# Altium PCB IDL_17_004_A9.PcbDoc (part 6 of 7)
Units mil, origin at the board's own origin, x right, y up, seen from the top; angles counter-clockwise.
Board outline 9493.25 x 7199.68 mil, 6 copper layers (Top Layer - SIG1, Layer 2 - GND1, Layer 3 - PWR1, Layer 4 - PWR2, Layer 5 - GND2, Bottom Layer - SIG2), stack 60.592 mil thick; 403 components, 274 nets, 1834 pads, 1849 vias.
Unrouted connection lines stored in the file: 1.
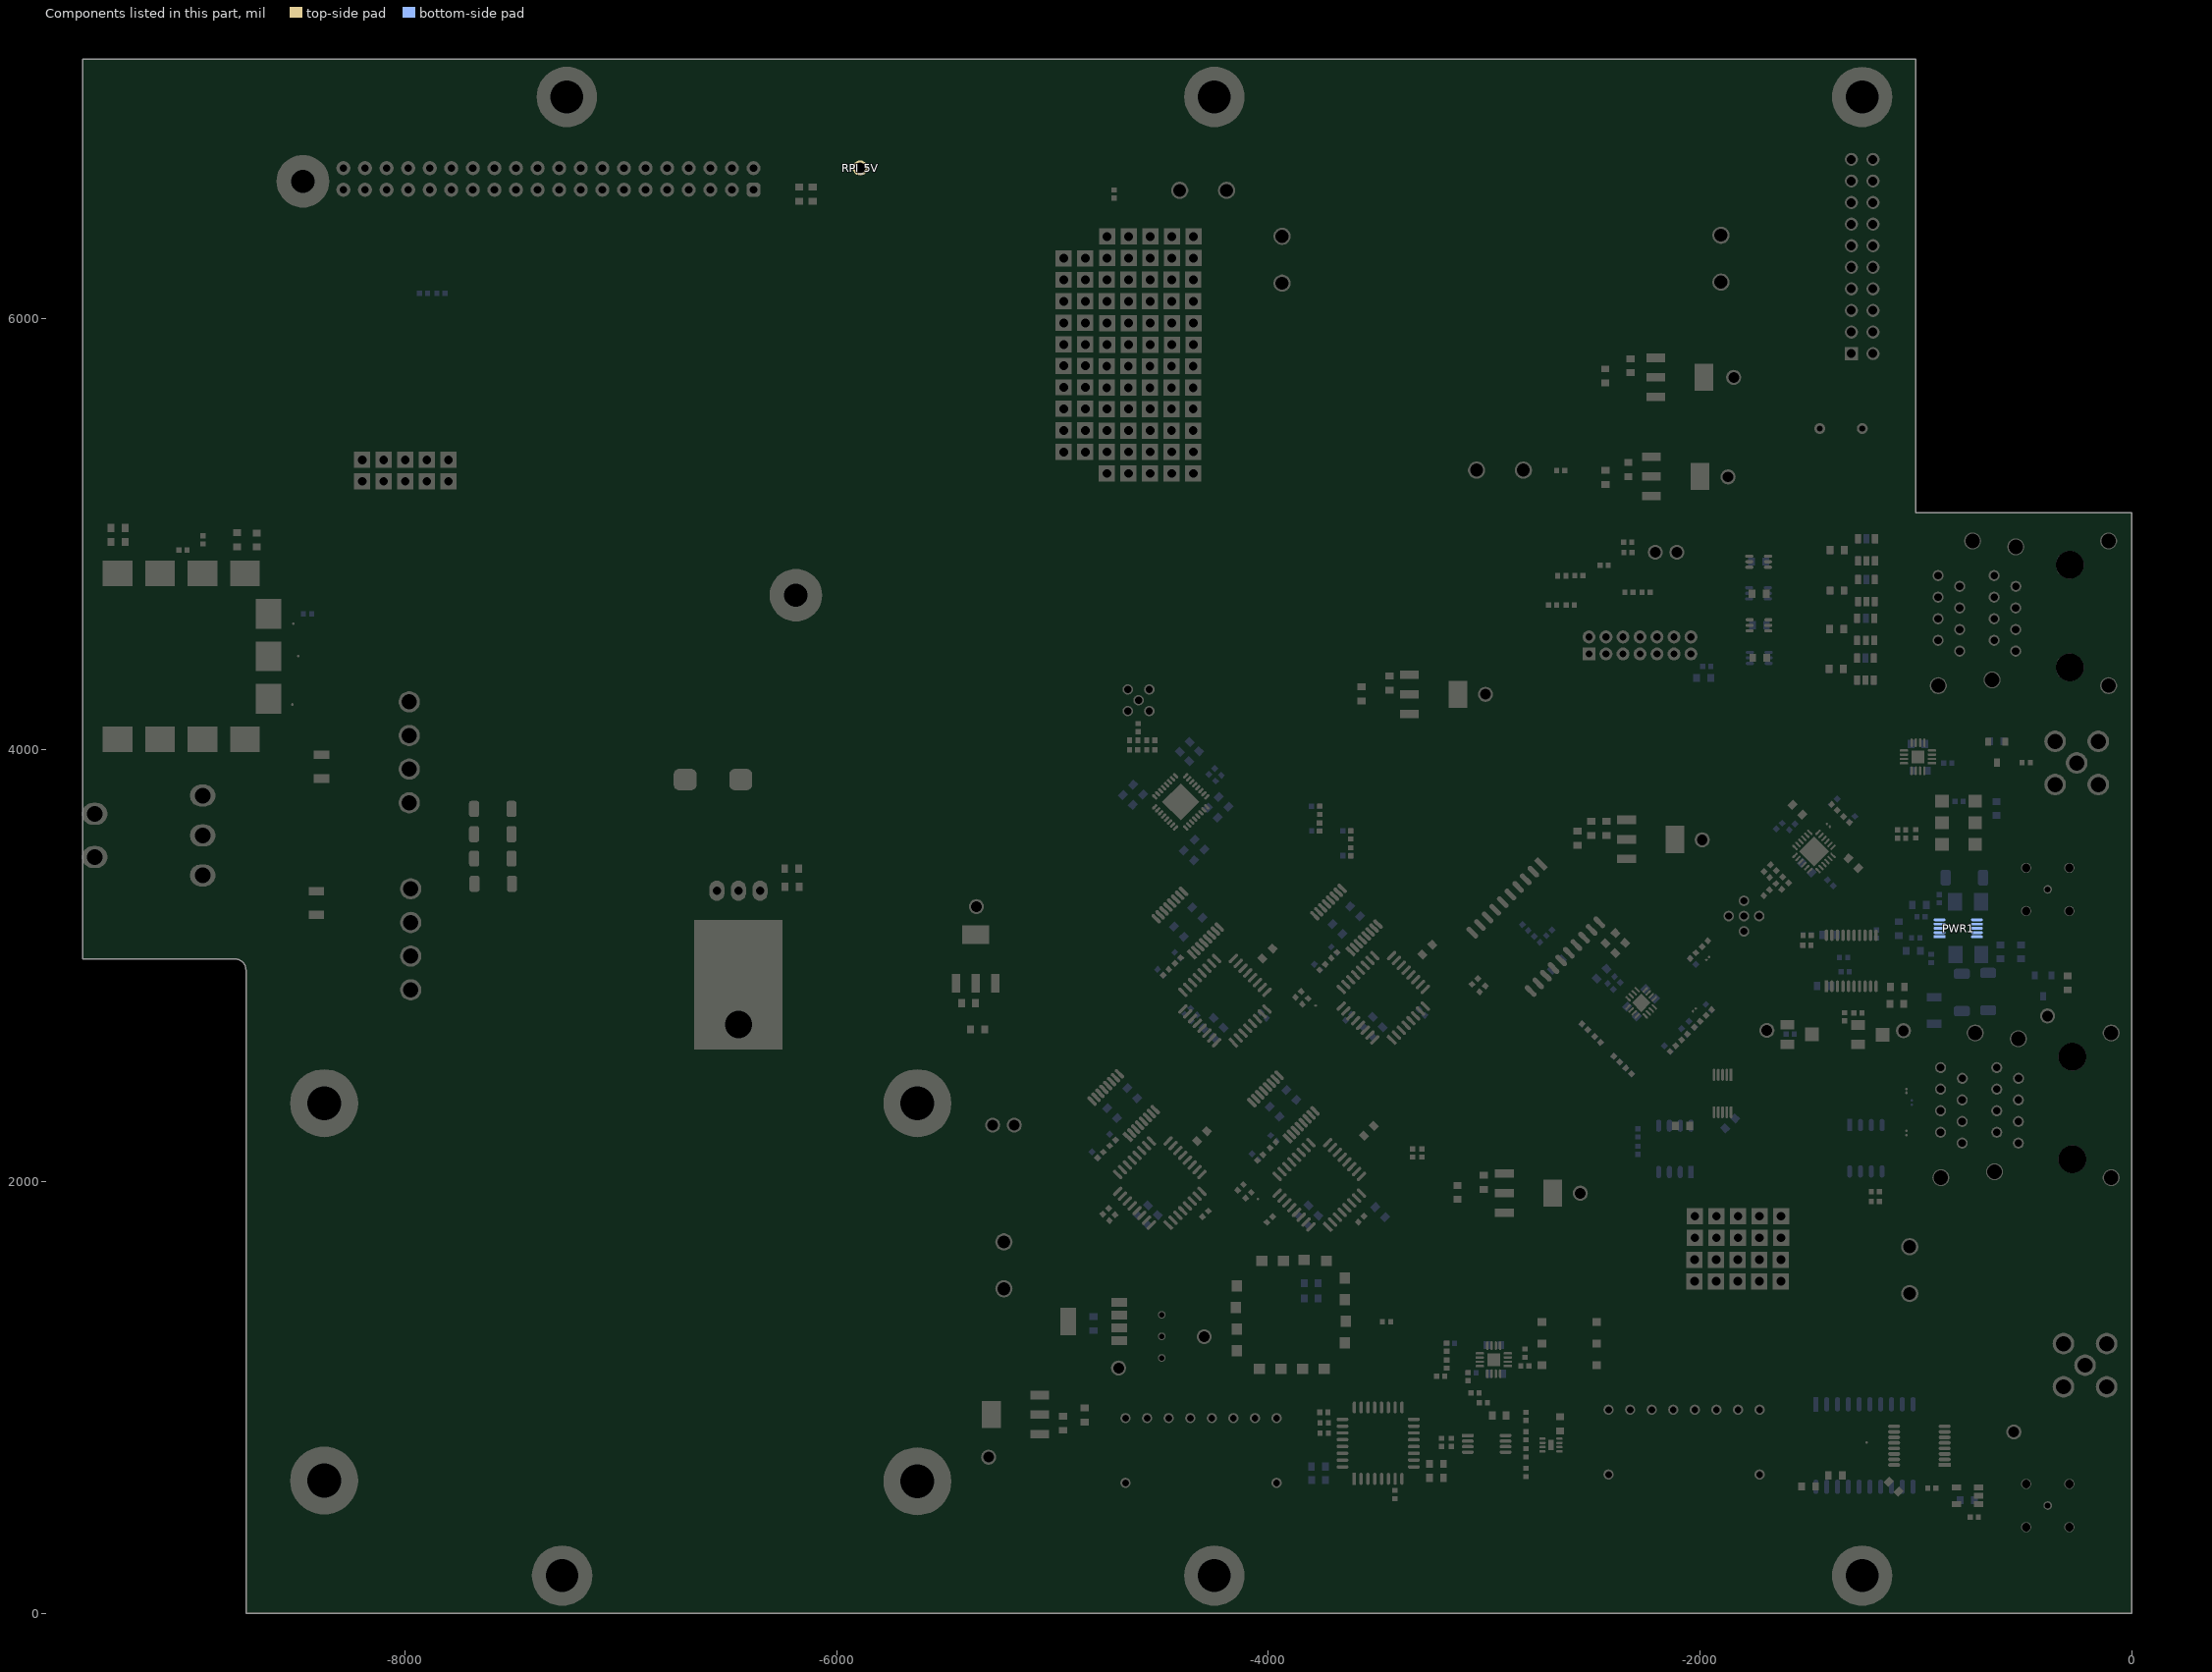
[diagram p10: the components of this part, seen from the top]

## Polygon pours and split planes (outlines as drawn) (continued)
RPI_5V on Layer 3 - PWR1 (split plane): -1020.57,7179.37 -1020.57,6052.09 -2668,6052.09 -2670.61,6051.74 -2673.04,6050.73 -2675.13,6049.13 -2676.74,6047.04 -2677.74,6044.61 -2678.09,6042 -2678.09,5501.17 -5556.91,5501.17 -5559.52,5500.83 -5561.96,5499.82 -5564.05,5498.22 -5575.13,5487.13 -5576.74,5485.04 -5577.74,5482.61 -5578.09,5480 -5578.09,4818.7 -5580.13,4817.13 -5581.74,4815.04 -5582.74,4812.61 -5583.09,4810 -5583.09,4194.17 -5583.13,4194.13 -5584.74,4192.04 -5585.74,4189.61 -5586.09,4187 -5586.09,3428 -5586.09,2538.17 -5586.13,2538.13 -5587.74,2536.04 -5588.74,2533.61 -5589.09,2531 -5589.09,1696.19 -5589.74,1694.61 -5589.87,1693.67 -5590.35,1693.04 -5591.35,1690.61 -5591.7,1688 -5591.35,1685.39 -5590.35,1682.96 -5590.09,1682.62 -5590.09,1125.19 -5590.74,1123.61 -5591.09,1121 -5591.09,19.96 -8716.11,19.88 -8714.77,2979.65 -8714.77,2979.66 -8714.96,2981.61 -8715.15,2983.58 -8715.72,2985.47 -8716.29,2987.35 -8716.3,2987.35 -8716.46,2987.67 -8716.48,2988 -8717.5,2994.9 -8719.2,3001.67 -8721.55,3008.24 -8724.53,3014.55 -8728.12,3020.53 -8732.28,3026.14 -8736.96,3031.31 -8742.14,3036 -8747.74,3040.16 -8753.73,3043.74 -8760.04,3046.73 -8766.61,3049.08 -8773.38,3050.77 -8780.28,3051.8 -8787.06,3052.13 -8787.25,3052.15 -8787.26,3052.15 -8787.27,3052.15 -9472.66,3051.48 -9473.15,7179.37
"RAW PWR" on Layer 4 - PWR2 (split plane): -1020.57,7179.37 -1020.57,5098.53 -1020.19,5094.61 -1019.04,5090.84 -1017.19,5087.37 -1014.69,5084.32 -1011.64,5081.82 -1008.17,5079.97 -1004.4,5078.82 -1000.48,5078.44 -20.12,5078.44 -20.1,20.1 -8716.11,19.88 -8714.77,2979.65 -8714.77,2979.66 -8714.96,2981.61 -8715.15,2983.58 -8715.72,2985.47 -8716.29,2987.35 -8716.3,2987.35 -8716.46,2987.67 -8716.48,2988 -8717.5,2994.9 -8719.2,3001.67 -8721.55,3008.24 -8724.53,3014.55 -8728.12,3020.53 -8732.28,3026.14 -8736.96,3031.31 -8742.14,3036 -8747.74,3040.16 -8753.73,3043.74 -8760.04,3046.73 -8766.61,3049.08 -8773.38,3050.77 -8780.28,3051.8 -8787.06,3052.13 -8787.25,3052.15 -8787.26,3052.15 -8787.27,3052.15 -9472.66,3051.48 -9473.15,7179.37
GND on Layer 5 - GND2 (split plane): -1020.57,7179.37 -1020.57,5098.53 -1020.19,5094.61 -1019.04,5090.84 -1017.19,5087.37 -1014.69,5084.32 -1011.64,5081.82 -1008.17,5079.97 -1004.4,5078.82 -1000.48,5078.44 -20.12,5078.44 -20.1,20.1 -8716.11,19.88 -8714.77,2979.65 -8714.77,2979.66 -8714.96,2981.61 -8715.15,2983.58 -8715.72,2985.47 -8716.29,2987.35 -8716.3,2987.35 -8716.46,2987.67 -8716.48,2988 -8717.5,2994.9 -8719.2,3001.67 -8721.55,3008.24 -8724.53,3014.55 -8728.12,3020.53 -8732.28,3026.14 -8736.96,3031.31 -8742.14,3036 -8747.74,3040.16 -8753.73,3043.74 -8760.04,3046.73 -8766.61,3049.08 -8773.38,3050.77 -8780.28,3051.8 -8787.06,3052.13 -8787.25,3052.15 -8787.26,3052.15 -8787.27,3052.15 -9472.66,3051.48 -9473.15,7179.37

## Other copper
Top Layer - SIG1:
  region net GND: -6245.22,6554.42 -6245.22,6433.18 -6077.92,6433.18 -6077.92,6554.42
  rectangle net JTAG_3V3: -8598.56,5000.27 -4971.56,5052.27
  rectangle net GND: -8808.78,4890.7 -8634.78,4947.76
  rectangle net JTAG_3V3: -9313.4,5000.34 -8596.4,5052.34
  rectangle net GND: -3144.97,1961.83 -3100.97,2067.83
  rectangle net "RAW PWR": -3147.07,1829.6 -3103.07,1935.6
  rectangle net GND: -2460,5278 -2418,5383
  rectangle net "RAW PWR": -2461.11,5142.48 -2417,5249
  rectangle net GND: -7531.91,3556.05 -7083.91,3764.38
  region net "RAW PWR": -7086.91,3331.05 -7086.91,3533.05 -7533.91,3533.05 -7533.91,3331.05
  region net GND: -6137,3213 -6251,3213 -6251,2610 -6137,2610
  region net GND: -6659.19,3213.23 -6773.19,3213.23 -6773.19,2613.23 -6659.19,2613.23
  region net GND: -6414,3742 -6497,3742 -6497,3199 -6414,3199
  region net RPI_5V: -6511.94,3736 -6773.19,3736 -6773.19,3282.23 -6511.94,3282.23
  rectangle net "RAW PWR": -6397,3253.23 -6219.97,3607
  region net GND: -2083.11,5382.76 -2461.11,5382.76 -2461.11,5317.08 -2083.11,5317.08
  region net "RAW PWR": -2083.11,5212.48 -2461.11,5212.48 -2461.11,5142.48 -2083.11,5142.48
  rectangle net 5VAUX: -5149.12,972.44 -4830.67,1042.44
  rectangle net GND: -5208.67,797.24 -4830.67,867.24
  rectangle net GND: -2463.93,5791.99 -2081.51,5861.99
  region net GND: -5407.71,2683.59 -5407.71,3061.59 -5470.98,3061.59 -5470.98,2683.59
  rectangle net "RAW PWR": -3146.94,1829.52 -2768.94,1890.92
  rectangle net GND: -3144.97,2008.52 -2766.97,2067.83
  region net "RAW PWR": -5233.66,2680.64 -5233.66,3058.64 -5303.66,3058.64 -5303.66,2680.64
  rectangle net "RAW PWR": -2461.93,5598.94 -2080.98,5668.94
  region net GND: -4888.6,1423.81 -5008.68,1423.81 -5008.68,1283.06 -4888.6,1283.06
  rectangle net GND: -3590.29,4325.17 -3212.29,4379.77
  rectangle net "RAW PWR": -3587.29,4132.77 -3209.29,4191.17
  rectangle net GND: -2589.43,3653.38 -2211.43,3714.08
  rectangle net "RAW PWR": -2586.43,3464.08 -2208.43,3534.08
  rectangle net 5VAUX: -4774.6,1358.06 -4461.6,1403.86
  rectangle net "RAW PWR": -4775.6,1416.06 -4462.6,1461.86
  rectangle net JTAG_3V3: -9312.36,4768.21 -9261.85,5051.31
  rectangle net NetJTAGDB_9: -9005.36,4832.21 -8866.36,4950.51
  rectangle net "RAW PWR": -2588.84,3465.38 -2544.84,3576.38
  rectangle net GND: -2589.6,3602.38 -2545.6,3713.38
  rectangle net "RAW PWR": -3589.75,4135.17 -3545.75,4246.17
  rectangle net GND: -3591.75,4269.17 -3547.75,4380.17
  region net RPI_5V: -6650,3736 -6650,3955 -6773,3955 -6773,3736
  region net GND: -6384,3667.43 -6384,3954.37 -6496.91,3954.37 -6496.91,3667.43
  region net GND: -6136,2617 -6136,3664 -6192,3664 -6192,2617
  region net GND: -6137,3654 -6137,3740 -6497,3740 -6497,3654
  rectangle net 5VAUX: -4872.35,934.35 -4830.35,1042.35
  rectangle net GND: -4872.67,797.24 -4830.67,905.24
  rectangle net "RAW PWR": -2461.93,5610.94 -2413.93,5719.94
  rectangle net GND: -2463.93,5737.94 -2415.93,5846.94
  rectangle net 3V3AUX: -3041.36,1225.35 -2980.5,1255.37
  rectangle net GND: -8740,0 0,360
  rectangle net GND: -9490,6840 -1000.48,7199.47
  rectangle net GND: -9417.73,4939.74 -9343.57,5050.98
  rectangle net GND: -6677.28,2583.15 -6214.6,2628.01
  rectangle net GND: -6686.79,3194.13 -6197.36,3239.09
  pour cut-out: -3609.85,1409.98 -3602.12,1406.78 -3595.47,1401.68 -3590.56,1395.27 -3498.05,1395.27 -3488.27,1395.92 -3487.16,1396.19 -3486.25,1396.18 -3483.67,1396.52 -3460.05,1396.52 -3451.75,1395.42 -3444.01,1392.22 -3437.37,1387.12 -3432.27,1380.48 -3429.07,1372.74 -3427.98,1364.44 -3427.98,1339.24 -3429.07,1330.94 -3432.27,1323.21 -3437.37,1316.56 -3444.01,1311.47 -3451.75,1308.26 -3460.05,1307.17 -3483.67,1307.17 -3491.97,1308.26 -3497.93,1310.73 -3590.56,1310.73 -3595.47,1304.32 -3602.12,1299.22 -3609.85,1296.02 -3618.15,1294.93 -3666.15,1294.93 -3674.46,1296.02 -3682.19,1299.22 -3688.83,1304.32 -3693.93,1310.96 -3697.14,1318.7 -3698.23,1327 -3698.23,1379 -3697.14,1387.3 -3693.93,1395.04 -3688.83,1401.68 -3682.19,1406.78 -3674.46,1409.98 -3666.15,1411.07 -3618.15,1411.07
  pour cut-out: -2705.63,1396.75 -2698.38,1393.75 -2692.15,1388.97 -2687.38,1382.75 -2684.37,1375.5 -2683.35,1367.72 -2683.35,1332.28 -2684.37,1324.5 -2687.38,1317.26 -2692.15,1311.03 -2698.38,1306.25 -2705.63,1303.25 -2713.41,1302.23 -2752.78,1302.23 -2760.56,1303.25 -2767.8,1306.25 -2774.03,1311.03 -2775.19,1312.55 -3408.83,1312.55 -3414.48,1310.21 -3422.26,1309.19 -3445.88,1309.19 -3453.66,1310.21 -3460.91,1313.21 -3467.13,1317.99 -3471.91,1324.22 -3474.91,1331.46 -3475.94,1339.24 -3475.94,1364.44 -3474.91,1372.22 -3471.91,1379.47 -3467.13,1385.69 -3460.91,1390.47 -3453.66,1393.47 -3445.88,1394.5 -3422.26,1394.5 -3414.48,1393.47 -3408.54,1391.01 -2771.36,1391.01 -2771.29,1391.07 -2770.78,1391.57 -2770.22,1391.89 -2767.8,1393.75 -2764.66,1395.05 -2763.96,1395.45 -2763.26,1395.63 -2760.56,1396.75 -2757.32,1397.18 -2756.36,1397.42 -2755.48,1397.42 -2752.78,1397.77 -2713.41,1397.77
  pour cut-out: -212.81,1232.23 -199.76,1230.51 -191.67,1228.35 -179.51,1223.31 -172.26,1219.12 -161.81,1211.11 -155.89,1205.19 -147.88,1194.74 -143.69,1187.49 -138.65,1175.33 -136.49,1167.24 -134.77,1154.19 -134.77,1145.81 -136.49,1132.76 -138.65,1124.67 -143.69,1112.51 -147.88,1105.26 -155.89,1094.81 -161.81,1088.89 -172.26,1080.88 -179.51,1076.69 -191.67,1071.65 -199.76,1069.49 -212.81,1067.77 -221.19,1067.77 -234.24,1069.49 -242.33,1071.65 -254.49,1076.69 -261.74,1080.88 -272.19,1088.89 -278.11,1094.81 -278.67,1095.55 -279.5,1096.37 -287.39,1103.21 -290.16,1105.25 -292.75,1106.93 -294.8,1108.05 -296.21,1108.67 -296.44,1108.75 -2437.9,1108.75 -2439.08,1107.85 -2439.53,1107.38 -2440.3,1106.91 -2443.43,1104.51 -2446.07,1103.41 -2446.69,1103.04 -2447.66,1102.76 -2451.17,1101.3 -2453.89,1100.94 -2454.73,1100.7 -2455.94,1100.67 -2459.47,1100.21 -2498.84,1100.21 -2507.14,1101.3 -2514.88,1104.51 -2521.52,1109.6 -2526.62,1116.25 -2529.82,1123.98 -2530.91,1132.28 -2530.91,1167.72 -2529.82,1176.02 -2526.62,1183.75 -2521.52,1190.4 -2514.88,1195.49 -2507.14,1198.7 -2498.84,1199.79 -2459.47,1199.79 -2455.94,1199.33 -2454.73,1199.3 -2453.89,1199.06 -2451.17,1198.7 -2447.66,1197.24 -2446.69,1196.96 -2446.07,1196.59 -2443.43,1195.49 -2440.3,1193.09 -2439.53,1192.62 -2439.08,1192.15 -2437.9,1191.25 -296.44,1191.25 -296.21,1191.33 -294.8,1191.95 -292.75,1193.07 -290.16,1194.75 -287.08,1197.02 -283.86,1199.68 -278.28,1204.96 -278.11,1205.19 -272.19,1211.11 -261.74,1219.12 -254.49,1223.31 -242.33,1228.35 -234.24,1230.51 -221.19,1232.23 -212.81,1232.23
  pour cut-out: -603.92,3991.45 -596.18,3988.25 -589.54,3983.15 -588.7,3982.06 -534.37,3982.06 -528.75,3984.39 -520.45,3985.48 -496.83,3985.48 -488.53,3984.39 -480.79,3981.19 -474.15,3976.09 -469.05,3969.45 -465.85,3961.71 -464.75,3953.41 -464.75,3928.21 -465.85,3919.91 -469.05,3912.18 -474.15,3905.53 -480.79,3900.44 -488.53,3897.23 -496.83,3896.14 -520.45,3896.14 -528.75,3897.23 -534.37,3899.56 -590.62,3899.56 -596.18,3895.29 -603.92,3892.09 -612.22,3891 -639.78,3891 -648.08,3892.09 -655.82,3895.29 -659.02,3897.75 -888,3897.75 -891.12,3898.16 -894.26,3898.37 -897.17,3898.94 -918.29,3901.43 -946,3901.43 -954.3,3902.52 -962.04,3905.72 -968.68,3910.82 -973.78,3917.46 -976.98,3925.2 -978.07,3933.5 -978.07,3944.5 -976.98,3952.8 -973.78,3960.54 -968.68,3967.18 -962.04,3972.28 -954.3,3975.48 -946,3976.57 -919.6,3976.57 -896.41,3979.21 -894.26,3979.63 -891.12,3979.84 -888,3980.25 -664.69,3980.25 -662.46,3983.15 -655.82,3988.25 -648.08,3991.45 -639.78,3992.55 -612.22,3992.55
  pour cut-out: -251.81,4022.23 -238.76,4020.51 -230.67,4018.35 -218.51,4013.31 -211.26,4009.12 -200.81,4001.11 -194.89,3995.19 -186.88,3984.74 -182.69,3977.49 -177.65,3965.33 -175.49,3957.24 -173.77,3944.19 -173.77,3935.81 -175.49,3922.76 -177.65,3914.67 -182.69,3902.51 -186.88,3895.26 -194.89,3884.81 -200.81,3878.89 -211.26,3870.88 -218.51,3866.69 -230.67,3861.65 -238.76,3859.49 -251.81,3857.77 -260.19,3857.77 -273.24,3859.49 -281.33,3861.65 -293.49,3866.69 -300.74,3870.88 -311.19,3878.89 -317.11,3884.81 -325.12,3895.26 -327.14,3898.75 -447.06,3898.75 -450.73,3897.23 -459.03,3896.14 -482.65,3896.14 -490.96,3897.23 -498.69,3900.44 -505.33,3905.53 -510.43,3912.18 -513.64,3919.91 -514.73,3928.21 -514.73,3953.41 -513.64,3961.71 -510.43,3969.45 -505.33,3976.09 -498.69,3981.19 -490.96,3984.39 -482.65,3985.48 -459.03,3985.48 -450.73,3984.39 -443.15,3981.25 -327.14,3981.25 -325.12,3984.74 -317.11,3995.19 -311.19,4001.11 -300.74,4009.12 -293.49,4013.31 -281.33,4018.35 -273.24,4020.51 -260.19,4022.23 -251.81,4022.23
  pour cut-out: -386.1,549.68 -384.14,549.55 -376.46,548.02 -374.59,547.39 -372.66,547 -370.89,546.13 -369.03,545.5 -367.39,544.41 -365.62,543.53 -359.11,539.18 -357.63,537.88 -355.99,536.79 -354.69,535.31 -353.21,534.01 -352.12,532.37 -350.82,530.89 -346.47,524.38 -345.59,522.61 -344.5,520.97 -343.87,519.11 -343,517.34 -342.61,515.41 -341.98,513.54 -340.45,505.86 -340.32,503.9 -339.94,501.97 -340.07,500 -339.94,498.03 -340.32,496.1 -340.45,494.14 -341.98,486.46 -342.61,484.59 -343,482.66 -343.87,480.89 -344.5,479.03 -345.59,477.39 -346.47,475.62 -350.82,469.11 -352.12,467.63 -353.21,465.99 -354.69,464.69 -355.99,463.21 -357.63,462.12 -359.11,460.82 -365.62,456.47 -367.39,455.59 -369.03,454.5 -370.89,453.87 -372.66,453 -374.59,452.61 -376.46,451.98 -384.14,450.45 -386.1,450.32 -388.03,449.94 -390,450.07 -391.97,449.94 -393.9,450.32 -395.86,450.45 -403.54,451.98 -405.41,452.61 -407.34,453 -409.11,453.87 -410.97,454.5 -412.61,455.59 -414.38,456.47 -420.89,460.82 -422.37,462.12 -424.01,463.21 -425.31,464.69 -426.79,465.99 -427.88,467.63 -429.18,469.11 -429.19,469.12 -668.89,469.12 -671.35,467.24 -670.76,465.81 -669.73,458.03 -669.73,432.83 -670.76,425.05 -673.76,417.8 -678.54,411.58 -684.76,406.8 -692.01,403.8 -699.79,402.78 -723.41,402.78 -731.19,403.8 -738.44,406.8 -744.66,411.58 -749.44,417.8 -752.44,425.05 -753.47,432.83 -753.47,458.03 -752.44,465.81 -750.75,469.9 -752.22,471.03 -757,477.25 -760,484.5 -761.03,492.28 -761.03,519.84 -760,527.62 -757,534.87 -752.22,541.09 -746,545.87 -738.75,548.87 -730.97,549.9 -687.66,549.9 -679.88,548.87 -672.63,545.87 -668.89,543 -415.18,543 -414.38,543.53 -412.61,544.41 -410.97,545.5 -409.11,546.13 -407.34,547 -405.41,547.39 -403.54,548.02 -395.86,549.55 -393.9,549.68 -391.97,550.06 -390,549.93 -388.03,550.06
  pour cut-out: -1294.46,4403.63 -1176.5,4403.63 -1175.52,4344.77 -1294.21,4344.77
  pour cut-out: -1293.84,4588.59 -1175.88,4588.59 -1174.9,4529.74 -1293.59,4529.74
  pour cut-out: -1289.79,4766.09 -1171.84,4766.09 -1170.85,4707.23 -1289.54,4707.23
  pour cut-out: -1288.17,4955.18 -1170.22,4955.18 -1169.24,4896.32 -1287.93,4896.32
  pour cut-out: -644.18,4066.63 -598.92,4065.53 -598.42,4009.09 -643.93,4009.46
  pour cut-out: -1581.7,3711.86 -1543.19,3753.39 -1518.91,3732.62 -1559.93,3692.61
  pour cut-out: -1321.96,3465.21 -1282.23,3506.33 -1259.25,3483.07 -1299.39,3442.24
  pour cut-out: -1103.26,2919.43 -1069.54,2919.43 -1069.54,2807.75 -1105.69,2807.75 -1105.69,2844.98 -1120.53,2844.98 -1120.53,2880.32 -1105.96,2880.32
  pour cut-out: -325.98,2937.72 -325.98,2937.91 -268.78,2937.91 -268.78,2904.54 -326.26,2904.54
  pour cut-out: -2472.14,5745.43 -2418.95,5745.43 -2418.95,5795.86 -2060.24,5795.86 -2060.24,5769.54 -2386.95,5769.54 -2386.95,5693.66 -2060.25,5693.66 -2053.06,5598.87 -2077.93,5598.87 -2077.93,5673.3 -2382.39,5673.3 -2418.95,5673.3 -2418.95,5719.25 -2472.14,5719.25
  pour cut-out: -2471.31,5276.64 -2416.48,5276.64 -2416.48,5327.07 -2070.82,5327.07 -2070.82,5299.46 -2384.48,5299.46 -2384.48,5224.86 -2057.78,5224.86 -2056.53,5204.51 -2379.92,5204.51 -2416.48,5204.51 -2416.48,5250.46 -2471.31,5250.46
  pour cut-out: -1230.35,2757.54 -1230.35,2757.5 -1175.02,2757.5 -1175.02,2603.5 -1230.97,2603.5 -1230.97,2662.46 -1310.87,2662.46 -1310.87,2699.82 -1231.47,2699.82
  pour cut-out: -2598.09,3602.94 -2545.51,3602.94 -2545.51,3653.37 -2205.04,3653.37 -2205.04,3627.05 -2523.01,3627.05 -2523.01,3551.16 -2196.32,3551.16 -2195.07,3530.81 -2518.46,3530.81 -2542,3530.81 -2542,3576.76 -2598.09,3576.76
  pour cut-out: -2084.89,1894.46 -1562.65,1894.46 -1562.65,1485.39 -2079.44,1485.39 -2084.89,1490.85
  pour cut-out: -3156.49,1961.53 -3100.55,1961.53 -3100.55,2008.48 -3080.47,2008.48 -2766.06,2008.48 -2766.06,1985.63 -3080.47,1985.63 -3080.47,1954.04 -3080.47,1909.75 -2757.33,1909.75 -2756.08,1889.4 -3079.47,1889.4 -3103.02,1889.4 -3103.02,1935.35 -3156.49,1935.35
  pour cut-out: -4990.4,5337.13 -4796.32,5330.07 -4796.32,5232.69 -4302.06,5238.33 -4301.16,5293.46 -4301.16,5343.98 -4301.16,6332.1 -5002.6,6332.1
  region net GND: -9065.24,4759.31 -9065.55,4886.38 -9047.3,4904.62 -9047.3,4949.38 -9080.76,4982.84 -9187.85,4982.84 -9205.9,4964.8 -9205.9,4878.95 -9203.13,4876.18 -9203.13,4759.31 -9201.89,4759.93 -9070.8,4759.93
  region net RPI_5V: -6518.61,6645.52 -6536.94,6663.84 -6536.94,6714.11 -6504.23,6746.81 -6133.89,6746.81 -6133.89,6632.18 -6190.13,6588.79 -6295.13,6588.79 -6351.86,6645.52
  region net DIS3V3: -1297.26,5583.46 -1234.18,5646.55 -1234.18,5858.12 -1208.94,5883.35 -1116.74,5883.35 -1080.84,5847.45 -1080.84,5522.32 -1204.09,5399.07 -1304.05,5399.07 -1340.93,5435.95 -1340.93,5538.82 -1290.47,5589.29
  region net RF_3V3: -4537.66,3706.45 -4509.14,3734.98 -4507.45,3734.98 -4502.88,3730.42 -4568.77,3664.53 -4614.14,3664.53 -4622.05,3672.44 -4622.06,3747.23 -4575.52,3793.76 -4563.76,3805.52 -4563.2,3804.96 -4540.08,3804.96 -4516.25,3781.12 -4516.25,3773.56 -4517.9,3771.91 -4524.66,3772.06 -4542.9,3790.3 -4552.67,3790.3 -4554.22,3790.16 -4554.37,3788.6 -4548.68,3782.69 -4532.94,3766.32 -4532.94,3757.77 -4542.33,3748.38 -4566.4,3748.38 -4573.73,3755.71 -4587.26,3755.71 -4598.73,3744.24 -4598.73,3717.71 -4587.48,3706.45
  region net 3V3AUX: -3697.83,615.63 -3652.65,660.81 -3636.64,660.81 -3622.36,646.54 -3622.36,630.18 -3667.88,584.73 -3688.16,584.73 -3697.83,594.4
  region net BMB_3V3: -3791.58,1717.3 -3781.58,1707.3 -3753.71,1707.3 -3743.35,1717.18 -3743.36,1764.01 -3725.68,1781.69 -3738.97,1794.98 -3766.44,1767.51 -3794.39,1795.46 -3807.27,1782.58 -3791.58,1766.89
  region net BMA_3V3: -4222.35,2598.52 -4213.27,2589.44 -4184.43,2589.44 -4176.52,2596.99 -4176.53,2632.7 -4157.95,2651.27 -4176.53,2669.31 -4187.57,2658.26 -4202.05,2643.79 -4223.11,2664.86 -4229.83,2665.17 -4242.08,2652.92 -4222.35,2633.18
  region net BMA_3V3: -3493.38,2601.91 -3486.8,2595.33 -3453.06,2595.33 -3445.16,2602.87 -3445.16,2638.58 -3427.49,2656.26 -3440.78,2669.55 -3468.25,2642.08 -3496.2,2670.03 -3509.07,2657.15 -3493.38,2641.46
  region net BMB_3V3: -4527.75,1729.36 -4513.21,1714.82 -4496.22,1714.82 -4479.52,1730.76 -4479.53,1772.2 -4461.85,1789.88 -4475.14,1803.17 -4502.61,1775.7 -4530.56,1803.65 -4543.44,1790.77 -4527.75,1775.08
  region net RPI_5V: -6196.77,6589.06 -6197.55,6589.06 -6224.04,6615.56 -6224.04,6746.81 -6070.45,6746.81 -6037.77,6714.14 -6037.77,6635.07 -6083.78,6589.06
  region net NetF0_1: -8449.01,3256.84 -8474.74,3231.11 -8474.74,3041.55 -8413.66,2980.46 -8095.44,2980.46 -7902.92,2980.46 -7844.79,3038.6 -7844.79,3246.66 -7872.66,3274.53 -7932.89,3274.53 -8386.55,3274.53
  region net NetD5_1: -9201.72,3638.31 -9201.72,3640.04 -9165.35,3676.4 -7869.08,3676.4 -7704.57,3840.91 -7650.15,3840.91 -7632.83,3823.6 -7636.3,3820.13 -7636.3,3295.44 -7660.54,3271.2 -7703.17,3271.2 -7962.92,3530.95 -9165.35,3530.95 -9198.26,3563.85 -9198.26,3643.5
  region net NetF1_1: -8423.48,3948.6 -8456.4,3981.52 -8456.4,4083.12 -8407.74,4131.78 -7914,4131.78 -7865.34,4083.12 -7865.34,3882.79 -7915.22,3832.92 -8173.28,3832.92 -8288.96,3948.6
  region net ACDC_PWR: -9205.1,3462.64 -9204.55,3462.64 -9172.3,3494.89 -9170.97,3493.55 -8415.19,3493.55 -8373.12,3451.49 -8373.12,3348 -8392.48,3328.64 -9183.65,3328.64 -9206.1,3351.08 -9206.1,3461.64
  region net NIM_PWR: -9189.08,3703.37 -9206.19,3720.47 -9209.19,3720.47 -9209.19,3865.86 -9187.58,3887.47 -8563.19,3887.47 -8562.29,3886.58 -8386.79,3886.58 -8351.51,3851.29 -8351.51,3720.47 -8368.61,3703.37
  region net DIS3V3: -2376.68,5765.24 -2377.68,5688.24 -2217.68,5688.24 -2052.68,5688.24 -2052.68,5613.24 -1902.68,5613.24 -1902.68,5838.24 -2052.68,5838.24 -2052.68,5763.24 -2377.68,5763.24
  region net RF_3V3: -3521.25,4291.69 -3521.25,4218.17 -3361.25,4218.17 -3196.25,4218.17 -3196.25,4143.17 -3046.25,4143.17 -3046.25,4368.17 -3196.25,4368.17 -3196.25,4293.17 -3521.25,4293.17
  region net BMA_3V3: -5393.02,2746.55 -5316.02,2745.55 -5316.02,2905.55 -5316.02,3070.55 -5241.02,3070.55 -5241.02,3220.55 -5466.02,3220.55 -5466.02,3070.55 -5391.02,3070.55 -5391.02,2745.55
  region net RM_3V3: -2516.84,3619.41 -2516.84,3550.38 -2356.84,3550.38 -2191.84,3550.38 -2191.84,3475.38 -2041.84,3475.38 -2041.84,3700.38 -2191.84,3700.38 -2191.84,3620.77 -2515.76,3620.77
  region net BMB_3V3: -3080,1987 -3081,1910 -2921,1910 -2756,1910 -2756,1835 -2606,1835 -2606,2060 -2756,2060 -2756,1985 -3081,1985
  region net JTAG_3V3: -2394.19,5288.72 -2394.78,5242.77 -2070,5242.77 -2070,5151 -1920,5151 -1920,5376 -2070,5376 -2070,5288.72
  region net 3V3AUX: -4896.12,880 -4895.12,957 -5055.12,957 -5220.12,957 -5220.12,1032 -5370.12,1032 -5370.12,807 -5220.12,807 -5220.12,882 -4895.12,882
  region net NetC28_2: -1182.75,2926.28 -1134.28,2926.28 -1125,2917 -1125,2688 -1133,2680 -1140,2687 -1174,2687 -1174,2780 -1152,2802 -1152,2856.57 -1182.36,2886.93
  region net NetB1_1: -918.22,3944.45 -889.91,3947.66 -889.91,3930.39 -918.22,3933.71
  pour cut-out: -4822.65,908.17 -4879.95,908.17 -4879.95,861.22 -4900.03,861.22 -5214.45,861.22 -5214.45,884.07 -4900.03,884.07 -4900.03,915.67 -4900.03,959.95 -5223.17,959.95 -5224.42,980.31 -4901.03,980.31 -4877.49,980.31 -4877.49,934.35 -4822.65,934.35
  pour cut-out: -5366.98,2677.3 -5366.45,2677.83 -5366.45,2726.89 -5413.4,2726.89 -5413.4,2746.97 -5413.4,3061.39 -5390.55,3061.39 -5390.55,2746.97 -5358.96,2746.97 -5314.67,2746.97 -5314.67,3070.12 -5294.32,3071.36 -5294.32,2747.98 -5294.32,2724.43 -5340.27,2724.43 -5340.27,2677.3
  pour cut-out: -3597.45,4276.53 -3590.53,4269.6 -3547.35,4269.6 -3547.35,4324.99 -3206.97,4325 -3206.97,4293.71 -3521.38,4293.71 -3521.38,4262.11 -3521.38,4217.83 -3198.24,4217.83 -3196.99,4197.47 -3520.38,4197.47 -3543.93,4197.47 -3543.93,4243.42 -3597.45,4243.42
  pour cut-out: -6202.28,6588.65 -6083.33,6588.86 -6028.22,6630.85 -6083.33,6558.8 -6082.93,6558.4 -6202.89,6558.4 -6224.1,6578.59
  pour cut-out: -4796.13,6424.54 -4301.05,6424.54 -4301.05,6331.84 -4795.08,6331.84 -4795.08,6332.37
  pour cut-out: -8246.77,5392.05 -7750.25,5392.05 -7750.25,5198.14 -8246.77,5198.14
  pour cut-out: -1359.76,3661.32 -1340.27,3661.32 cw(c-1340.27,3640) -1318.95,3640 cw(c-1331.9,3640) -1331.9,3627.06 -1340.88,3627.06 cw(c-1340.88,3652.34) -1366.16,3652.34
  pour cut-out: -8742.67,-0.11 -8736.07,2997.05 ccw(c-8796.62,2968.44) -8774.06,3031.5 -9501.28,3031.49 -9501.28,-0.12
  region net RF_3V3: -1567,3459 ccw(c-1567,3463.83) -1563.59,3460.41 -1529,3495 cw(c-1526.59,3492.59) -1526.59,3496 -1524,3496 cw(c-1524,3491.18) -1520.59,3494.59 -1511.2,3485.2 cw(c-1521.35,3477.99) -1514.24,3467.76 -1532.43,3449.57 cw(c-1555,3458.14) -1555,3434 cw(c-1555,3438.83) -1558.41,3435.41 -1568,3445 cw(c-1563.17,3449.83) -1570,3449.83 -1570,3456 cw(c-1567.49,3456.5) -1570,3457 cw(c-1567.88,3455.58) -1569.29,3457.71 -1565,3459 -1568,3459
Bottom Layer - SIG2:
  rectangle net GND: -3876.54,594.58 -3795.57,700.58
  rectangle net 3V3AUX: -3744,591.82 -3593.04,702.39
  rectangle net GND: -7531.91,3556.05 -7088.91,3764.38
  rectangle net "RAW PWR": -7533.91,3331.05 -7086.91,3533.05
  rectangle net RM_3V3: -824.11,3012.63 -784.43,3336.37
  rectangle net GND: -1577,5398 -1379,5584
  rectangle net NetC122_1: -996.63,3040.22 -869.63,3141.22
  rectangle net NetC120_2: -819,2943.76 -581,2983.13
  region net NetC120_2: -579.85,2944 -579.85,3052.13 -640,3052.13 -640,2944
  rectangle net GND: -8740,0 0,360
  rectangle net GND: -9490,6840 -1000.48,7199.47
  pour cut-out: -4311.75,3963.14 -4335.61,3939.6 -4418.72,4023.04 -4395.1,4046.82
  pour cut-out: -4377.08,3479.67 -4400.62,3503.53 -4310.03,3593.75 -4286.25,3570.13
  pour cut-out: -4266.35,3677.78 -4289.89,3701.64 -4199.59,3791.59 -4175.81,3767.97
  pour cut-out: -4595.63,3849.28 -4570.38,3823.68 -4658.57,3735.85 -4684.08,3761.19
  pour cut-out: -4839.79,1326.53 -4839.56,1360.05 -4782.37,1359.93 -4782.25,1326.42
  pour cut-out: -3818.35,1559.26 -3784.83,1559.03 -3785.08,1430.96 -3818.6,1430.84
  pour cut-out: -1829.9,2262.09 -1853.76,2238.55 -1894.13,2279.07 -1870.51,2302.85
  pour cut-out: -2324.1,2755.87 -2347.64,2779.73 -2307.12,2820.09 -2283.33,2796.48
  pour cut-out: -2239.61,2838.24 -2263.15,2862.1 -2222.62,2902.47 -2198.84,2878.85
  pour cut-out: -2696.31,3014.19 -2672.45,3037.72 -2632.09,2997.2 -2655.71,2973.42
  pour cut-out: -2488.48,2971.82 -2464.62,2995.35 -2424.26,2954.83 -2447.88,2931.05
  pour cut-out: -2972.17,1272.79 -2938.66,1272.56 -2938.77,1215.37 -2972.29,1215.25
  pour cut-out: -2962.58,1139.81 -2929.06,1139.58 -2929.17,1082.38 -2962.69,1082.27
  pour cut-out: -3737.05,666.73 -3737.28,633.22 -3794.47,633.33 -3794.59,666.85
  pour cut-out: -1746.2,4901.25 -1712.68,4901.02 -1712.8,4843.82 -1746.31,4843.71
  pour cut-out: -1742.66,4606.47 -1709.14,4606.24 -1709.25,4549.05 -1742.77,4548.93
  pour cut-out: -1382.47,4954.11 -1348.95,4953.88 -1349.06,4896.69 -1382.58,4896.57
  pour cut-out: -1382.49,4767.39 -1348.97,4767.16 -1349.09,4709.97 -1382.6,4709.85
  pour cut-out: -1384.61,4588.85 -1351.1,4588.62 -1351.21,4531.42 -1384.73,4531.31
  pour cut-out: -1386.66,4404.84 -1353.14,4404.61 -1353.25,4347.41 -1386.77,4347.3
  pour cut-out: -656.29,3746.25 -597.6,3746.67 -597.6,3710.13 -656.29,3709.16
  pour cut-out: -542.88,3081.92 -542.79,3048.07 -485.69,3048.26 -485.97,3081.83
  pour cut-out: -654.98,3079.05 -619.79,3080.34 -580.74,3081.08 -580.37,3051.78 -643.74,3052.52 -657.01,3045.7 -659.59,3070.02
  pour cut-out: -774.79,3091.31 -762.01,3091.31 -754.09,3091.31 -734.43,3057 -727.55,3004.59 -695.57,3002.79 -701.26,2990.23 -742.3,2987.05 -778.97,2993.24
  pour cut-out: -1109.33,3189.1 -1026.69,3189.24 -1025.31,3157.82 -1053.27,3158.93 -1052.44,3155.05 -1099.91,3154.36 -1106.28,3157.13 -1122.34,3158.93 -1124.69,3183.56 -1119.01,3189.52 -1108.08,3189.38
  pour cut-out: -1416.75,3172.62 -1383.41,3172.77 -1382.8,3115.22 -1417.67,3114.91
  pour cut-out: -1464.96,3172.55 -1447.98,3169.46 -1447.98,3071.36 -1464.96,3070.97
  pour cut-out: -1292.61,4589.64 -1174.65,4589.64 -1173.67,4530.78 -1292.36,4530.78
  pour cut-out: -779.19,543.61 -746.96,543.81 -746.71,496.84 -780.21,497.65
  pour cut-out: -3785.34,710.02 -3752.05,710.02 -3750.41,586.97 -3784.36,588.93
  pour cut-out: -3996.51,2322.27 -3892.5,2426.37 -3867.54,2403.76 -3974.91,2296.9
  pour cut-out: -4749.19,2315.84 -4629.99,2434.49 -4605.3,2410.54 -4725.61,2291.71
  pour cut-out: -1294.71,4404.72 -1176.76,4404.72 -1175.78,4345.87 -1294.47,4345.87
  pour cut-out: -1289.14,4766.54 -1171.19,4766.54 -1170.2,4707.69 -1288.89,4707.69
  pour cut-out: -1288.47,4955.14 -1170.52,4955.14 -1169.54,4896.29 -1288.22,4896.29
  pour cut-out: -2084.38,1892.51 -1562.13,1892.51 -1562.13,1483.44 -2078.92,1483.44 -2084.38,1488.89
  pour cut-out: -5005.01,6335.4 -5004.63,6335.77 -4300.5,6335.77 -4300.5,5328.5 -4303.1,5325.9 -5000.51,5325.9
  region net RPI_5V: -6518.61,6645.52 -6536.94,6663.84 -6536.94,6750.5 -6051.54,6750.5 -6051.54,6647.33 -6072.49,6631.16 -6337.5,6631.16 -6351.86,6645.52
  region net NetC120_1: -730.02,3068.65 -722.87,3075.8 -657.96,3075.8 -639.31,3094.46 -589.99,3094.46 -586.87,3097.58 -586.87,3127.63 -593.88,3134.63 -641.98,3134.63 -741.27,3134.63 -743.44,3132.46 -743.44,3082.07
  region net -5V: -447.09,2973.72 -497.03,3040.71 -527.12,3040.58 -531.58,3036.12 -531.58,2943.15 -513.29,2924.86 -458.03,2924.86 -447.09,2936.9
  region net GND: -3832.12,1899.28 -3760.83,1828 -3711.82,1844.47 -3693.23,1887.43 -3720.19,1914.39 -3824.34,1914.39 -3832.11,1906.61
  region net BMB_3V3: -3882.19,1855.98 -3869.95,1855.98 -3800.6,1786.63 -3725.79,1786.63 -3718.18,1779.02 -3718.18,1737.82 -3733.22,1722.87 -3838.34,1722.87 -3894.93,1779.45 -3894.93,1843.24
  region net GND: -4571.96,1902.04 -4500.68,1830.75 -4451.67,1847.22 -4433.08,1890.18 -4460.04,1917.14 -4564.18,1917.14 -4571.96,1909.37
  region net GND: -4272.4,2763.42 -4201.11,2692.13 -4133.52,2692.13 -4101.03,2719.07 -4101.03,2729.14 -4160.96,2789.07 -4254.07,2789.07 -4272.4,2770.74
  region net BMB_3V3: -4621.31,1859.96 -4595.29,1859.96 -4525.94,1790.61 -4464.9,1790.61 -4457.29,1783.01 -4457.29,1741.81 -4472.33,1726.85 -4577.45,1726.85 -4634.04,1783.44 -4634.04,1847.23
  region net BMA_3V3: -4317.32,2724.2 -4305.08,2724.2 -4235.73,2654.85 -4160.92,2654.85 -4153.31,2647.24 -4153.31,2606.05 -4168.35,2591.09 -4273.47,2591.09 -4330.06,2647.68 -4330.06,2711.47
  region net BMA_3V3: -3596.99,2708.35 -3580.06,2725.28 -3566.5,2725.28 -3500.56,2659.34 -3424.15,2659.34 -3413.26,2649.58 -3413.26,2603.17 -3420.79,2595.64 -3535.07,2595.64 -3596.99,2657.56
  region net GND: -3537.29,2763.23 -3462.46,2688.4 -3382.87,2688.4 -3332.31,2738.95 -3332.31,2743.73 -3394.26,2805.69 -3506.67,2805.69 -3537.29,2775.07
  region net GND: -6774.46,3169.66 -6730.42,3213.69 -6183.77,3213.69 -6135.17,3165.1 -6135.17,2651.85 -6174.65,2612.37 -6715.24,2612.37 -6774.46,2671.59
  region net "RAW PWR": -6378.02,3270.75 -6395.45,3292.32 -6395.45,3320.89 -6395.45,3583.18 -6373.59,3605.04 -6372.3,3603.75 -6230.87,3603.75 -6221.01,3593.9 -6221.01,3290.03 -6242.63,3270.75 -6248.02,3270.75
  region net RPI_5V: -6546.41,3735.38 -6649.66,3735.38 -6650.8,3736.52 -6650.8,3936.74 -6670.62,3956.56 -6748.04,3956.56 -6773.99,3930.61 -6772.11,3928.72 -6772.11,3307.05 -6746.96,3281.91 -6540.46,3281.91 -6540.46,3282.61 -6511.42,3311.66 -6511.42,3698.82
  region net NetF0_1: -8449.01,3256.84 -8474.74,3231.11 -8474.74,3041.32 -8411.12,2977.7 -8098.2,2977.7 -8095.44,2980.46 -7902.92,2980.46 -7844.79,3038.6 -7844.79,3246.66 -7872.66,3274.53 -7932.89,3274.53 -8386.55,3274.53
  region net NetD5_1: -9198.26,3643.5 -9165.35,3676.4 -7869.08,3676.4 -7704.57,3840.91 -7650.15,3840.91 -7632.83,3823.6 -7636.3,3820.13 -7636.3,3295.44 -7660.54,3271.2 -7703.17,3271.2 -7962.92,3530.95 -9165.35,3530.95 -9198.26,3563.85
  region net NIM_PWR: -9189.08,3703.37 -9206.19,3720.47 -9209.19,3720.47 -9209.19,3865.86 -9187.58,3887.47 -8563.19,3887.47 -8562.29,3886.58 -8386.79,3886.58 -8351.51,3851.29 -8351.51,3720.47 -8368.61,3703.37
  region net ACDC_PWR: -9205.1,3462.64 -9204.55,3462.64 -9172.3,3494.89 -9170.97,3493.55 -8415.19,3493.55 -8373.12,3451.49 -8373.12,3348 -8392.48,3328.64 -9183.65,3328.64 -9206.1,3351.08 -9206.1,3461.64
  region net NetF1_1: -8423.48,3948.6 -8456.4,3981.51 -8456.4,4083.12 -8407.74,4131.78 -7914,4131.78 -7865.34,4083.12 -7865.34,3882.79 -7915.22,3832.92 -8173.28,3832.92 -8288.96,3948.6
  region net -5V: -704,2792.73 -689.73,2807 -633.42,2807 -620.42,2794 -425,2794 -412,2807 -360,2807 -344,2791 -344,2748 -360,2732 -682,2732 -704,2754
  pour cut-out: -8742.67,-0.11 -8736.07,2997.05 ccw(c-8796.62,2968.44) -8774.06,3031.5 -9501.28,3031.49 -9501.28,-0.12
Layer 3 - PWR1 (plane layer: these items are gaps in the copper):
  lines w20: -5581.61,1688 -490,1688 ; -5581,-4 -5581,1121 -5580,1121 ; -5579,2527 -3595,2527 ; -5579,2531 -5579,1692 -5580,1692 -5580,1121 ; -5576,2538 -5576,3428 -5576,4187 ; -5576,3424 -4041,3424 ; -5573,4187 -5573,4810 ; -5568,4810 -5568,5480 -5556.91,5491.09 -2662,5491.09 -2657.91,5491.09 ; -5562.91,4806 -2664,4806 ; -3632,1688 -3632,977 -5174,977 -5174,1121 -5580,1121 ; -3591,2524 -3190,2123 -2501,2123 -2359,1981 -1491,1981 -1353,2119 -1353,2266 ; -3458,3422 -2476,2440 -2364,2440 -1929,2440 -1929,2266 -1132,2266 -1132,2720 -1135,2720 ; -3458,3424 -4041,3424 ; -2664,4795.91 -2662,4795.91 -2662,4325 3,4325 ; -1135.25,3075.75 -218,3075.75 -218,3075 ; -1134,3069.75 -1134,2711 -490,2711 -490,1032.52 -839,1032.52 -839,0 ; -1003,6046 -1003,6042 -2668,6042 -2668,5493 -2491,5493 -1654,5493 -1654,5297 -1001,5297 ; -719,0 -719,905.09 -218,905.09 -218,3321 -1146,3321 ; 1,3526 -1146,3526 -1146,3321 ; -4041,3424 -4041,3886 -1856,3886 -1856,3321 -1146,3321

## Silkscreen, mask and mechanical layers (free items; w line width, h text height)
Top Overlay:
  drawing of 177 lines, arcs and shapes, not listed
  text "IDL" at -3687.98,6379.19 h400
  text "5V" at -4279,6334 h60
  text "Instrumentation Development Lab" at -3686.86,6291.53 h100
  text "UART(TX)" at -5465,6236 h37
  text "X-Ray Timing Distribution Module. Rev B" at -3689.93,6204.44 h100
  text "IDL_17_004, Jan 2017" at -3687.12,6122.34 h100
  text "GPIO_07" at -5484,6085 h37
  text "UART(RX)" at -5462,5991 h37
  text "JDC, KPL, mza" at -3729.8,5984.09 h100
  text "GPIO_01" at -5491,5885 h37
  text "GND" at -5185,5841 h37
  text "GND" at -5184,5742 h37
  text "GPIO_12" at -5486,5630 h37
  text "ID_EPROM" at -5476.92,5490.2 h37
  text "GND" at -7759.52,5419.04 h37 r90
  text "GND" at -8156.42,5415.66 h37 r90
  text "GPIO_26" at -7904.95,5397.48 h37 r90
  text "GPIO_07" at -8005.16,5396.57 h37 r90
  text "GPIO_21" at -7805.16,5389.57 h37 r90
  text "IC_EPROM" at -5480.02,5382.89 h37
  text "GPIO_13" at -5487,5286 h37
  text "GND" at -4284,5241 h60
  text "Install J13 to Enable SCROD 2" at -2746.55,4119.56 h100
  text "NIM PWR" at -7658.29,3962.9 h60
  text "EXT DC/AC / PWR" at -7727.25,3037.85 h60
  text "Install J14 to / enable Testing Sig" at -5723.54,1976.92 h100
  text "3.3V" at -1938.29,1883.93 h60
  text "GND" at -1943.13,1365.59 h60
  text "Set to 99 binary" at -2664.07,471.17 h60
  text "Set to 25 binary" at -4993.17,437.42 h60
Top Solder:
  rectangle: -8740,0 0,360
  rectangle: -9490,6840 -1000,7200.07
Bottom Solder:
  rectangle: -8740,0 0,360
  rectangle: -9490,6840 -1000,7200
Board Outline:
  lines w20: -8785.16,3034.04 cw(c-8785.16,2984.04) -8735.16,2984.04 -8735.16,2955.53 ; -8782.5,3034.2 -9490,3034.2 -9490,7200 -7999.76,7200 ; -8735.35,2956.71 -8735.35,2868.14 -8735.4,2868.19 -8735.4,0 0.24,0 0,5099.89 -1000,5099.89 -1000,7199.89 -7999.76,7199.89
Sheet Top:
  lines w3.9: -13496,-1693 -13496,10786.9 3303.91,10786.9 3303.91,-1693 -13496,-1693 ; -13396,-1593.3 -13396,10687.2 3203.65,10687.2 3203.65,-1593.3 -13396,-1593.3
  lines w3.94: -3486,-1593.3 -3486,-883.1 3203.65,-883.1 ; -3486,-1242.34 3204,-1242.34 ; -3486,-1123.1 1334,-1123.1 ; -3486,-1003.1 1334,-1003.1 ; -1981,-1242.34 -1981,-883.1 ; -981,-1242.34 -981,-883.1 ; 609,-1242.34 609,-883.1 ; 1334,-1593.3 1334,-883.1 ; 1334,-1063.1 3203.65,-1063.1
  text "Designer:" at -3461,-973.1 h100
  text "KHANH LE" at -2896,-978.1 h100
  text "Revision:" at -1956,-978.1 h100
  text "REV B" at -1396,-978.1 h100
  text "File:" at -956,-978.1 h100
  text "idl_17_001_A9" at -756,-978.1 h100
  text "Sheet  1 of  1" at 639,-978.1 h100
  text "Code:" at 1359,-1023.1 h100
  text "Drawn By:" at -3461,-1093.1 h100
  text "JULIEN C" at -2896,-1093.1 h100
  text "Modif. Date:" at -1956,-1098.1 h100
  text "Date" at -1451,-1098.1 h100
  text "Variant:" at -956,-1098.1 h100
  text ".VariantName" at -591,-1098.1 h100
  text "ID:" at 1364,-1203.1 h100
  text "Approved By:" at -3461,-1213.1 h100
  text ".Approved_By" at -2896,-1213.1 h100
  text "Print Date:" at -1956,-1218.1 h100
  text ".Print_Date" at -1451,-1218.1 h100
  text ".Approved_By" at -956,-1218.1 h100
  text "Size:  A3 H" at 639,-1218.1 h100
  text "Title:" at -3461,-1343.1 h100
  text "University of Hawaii at Manoa" at 1365.42,-1351.37 h100
  text "High Energy Physics Group" at 1365.42,-1449.79 h100
  text "XTD MODULE" at -3236,-1483.1 h160
  text "Instrumentation Development Laboratory" at 1365.42,-1552.15 h100
Sheet Bot:
  lines w3.9: -13496,-1692.8 3303.65,-1692.8 3303.65,10787.1 -13496,10787.1 -13496,-1692.8 ; -13396,-1593.1 3203.38,-1593.1 3203.38,10687.4 -13396,10687.4 -13396,-1593.1
  lines w3.94: -13396,-1242.14 -5706.35,-1242.14 ; -13396,-1062.9 -10526.35,-1062.9 ; -13396,-882.9 -5706.35,-882.9 -5706.35,-1593.1 ; -10526.35,-1593.1 -10526.35,-882.9 ; -10526.35,-1122.9 -5706.35,-1122.9 ; -10526.35,-1002.9 -5706.35,-1002.9 ; -9801.35,-1242.14 -9801.35,-882.9 ; -8211.35,-1242.14 -8211.35,-882.9 ; -7211.35,-1242.14 -7211.35,-882.9
  text "Designer:" at -5731.35,-972.9 h100
  text "Sheet  1 of  1" at -9831.35,-977.9 h100
  text ".Pcb_File_Name_No_Path" at -8436.35,-977.9 h100
  text "File:" at -8236.35,-977.9 h100
  text ".Version" at -7796.35,-977.9 h100
  text "Revision:" at -7236.35,-977.9 h100
  text ".Designer" at -6296.35,-977.9 h100
  text "Code:" at -10551.35,-1022.9 h100
  text ".Drawn_By" at -6296.35,-1092.9 h100
  text "Drawn By:" at -5731.35,-1092.9 h100
  text ".VariantName" at -8601.35,-1097.9 h100
  text "Variant:" at -8236.35,-1097.9 h100
  text "Date" at -7741.35,-1097.9 h100
  text "Modif. Date:" at -7236.35,-1097.9 h100
  text "ID:" at -10556.35,-1202.9 h100
  text ".Approved_By" at -6296.35,-1212.9 h100
  text "Approved By:" at -5731.35,-1212.9 h100
  text "Size:  A3 H" at -9831.35,-1217.9 h100
  text "Signature:" at -8236.35,-1217.9 h100
  text ".Print_Date" at -7741.35,-1217.9 h100
  text "Print Date:" at -7236.35,-1217.9 h100
  text "Title:" at -5731.35,-1342.9 h100
  text "University of Hawaii at Manoa" at -10559.7,-1355.31 h100
  text "High Energy Physics Group" at -10559.7,-1453.73 h100
  text ".Printout_Name" at -5956.35,-1482.9 h160
  text "Instrumentation Development Laboratory" at -10559.7,-1556.09 h100
FabNTop:
  text ".IDLnum" at 1659,-1023.1 h100
  text "ASSEMBLY" at 639.04,-1099.4 h100
  text ".BoardName" at 1659,-1203.1 h100
FabNBot:
  text ".IDLnum" at -10851.35,-1022.9 h100
  text "ASSEMBLY" at -9831.43,-1099.4 h100
  text ".BoardName" at -10851.35,-1202.9 h100
PCBNTop:
  text ".IDLnum" at 1659,-1023.1 h100
  text "PCB" at 639.04,-1099.4 h100
  text ".BoardName" at 1659,-1203.1 h100
PCBNBot:
  text ".IDLnum" at -10851.12,-1022.62 h100
  text "PCB" at -9831.43,-1099.4 h100
  text ".BoardName" at -10851.35,-1202.9 h100
Dimensions:
  lines w5: -9487.2,7199.89 -8299.76,7199.89 ; -8824.8,-300.11 -8824.8,-0.11 -8299.76,-0.11 ; -999.76,7199.89 -999.76,7498.63 ; 0.24,-300.11 0.24,-0.11 2700.24,-0.11 ; 0.24,7499.89 0.24,7199.89 298.99,7199.89 ; 124.76,3939.11 868,3939 ; 150.24,6829.89 2700.24,6829.89 ; 150.7,2353.89 1501.24,2353.89 ; 151.42,499.89 2100.24,499.89 ; 155,3356 1206.24,3354.89 ; 155.24,5449.89 2400.24,5449.89 ; 172.65,1153.15 1823.9,1153.15
  lines w8: 163,4630 600.24,4630
  lines w10: -9487.23,7509.89 -9487.17,7489.89 ; -9427.26,7520.07 -9487.2,7499.89 ; -9427.14,7480.07 -9487.2,7499.89 ; -8817.93,-295.43 -8817.9,-275.43 ; -8757.95,-305.53 -8817.91,-285.43 ; -8757.88,-265.53 -8817.91,-285.43 ; -5608.87,7511.53 -9487.2,7499.89 ; -4877.1,7513.72 -998.77,7525.36 ; -4794.72,-292.13 -8817.91,-285.43 ; -4022.96,-293.42 0.24,-300.11 ; -1058.83,7545.18 -998.77,7525.36 ; -1058.71,7505.18 -998.77,7525.36 ; -998.8,7535.36 -998.74,7515.36 ; -998.08,7512.99 -998.08,7532.99 ; -938.08,7502.99 -998.08,7522.99 ; -938.08,7542.99 -998.08,7522.99 ; -774,7522.99 -998.08,7522.99 ; -222.17,7522.99 1.92,7522.99 ; -59.79,-320.01 0.24,-300.11 ; -59.72,-280.01 0.24,-300.11 ; -58.08,7502.99 1.92,7522.99 ; -58.08,7542.99 1.92,7522.99 ; 0.23,-310.11 0.26,-290.11 ; 1.92,7512.99 1.92,7532.99 ; 280.24,59.89 300.24,-0.11 ; 280.24,5039.89 300.24,5099.89 ; 280.24,5159.89 300.24,5099.89 ; 280.24,7139.89 300.24,7199.89 ; 290.24,-0.11 310.24,-0.11 ; 290.24,7199.89 310.24,7199.89 ; 300.24,2273.97 300.24,-0.11 ; 300.24,2825.8 300.24,5099.89 ; 300.24,5873.97 300.24,5099.89 ; 300.24,6425.8 300.24,7199.89 ; 320.24,59.89 300.24,-0.11 ; 320.24,5039.89 300.24,5099.89 ; 320.24,5159.89 300.24,5099.89 ; 320.24,7139.89 300.24,7199.89 ; 580.24,60 600.24,0 ; 580.24,4573 600.24,4633 ; 590.24,0 610.24,0 ; 590.24,4633 610.24,4633 ; 600.24,2035.59 600.24,0 ; 600.24,2597.41 600.24,4633 ; 620.24,60 600.24,0 ; 620.24,4573 600.24,4633 ; 880.24,60 900.24,0 ; 880.24,3880 900.24,3940 ; 890.24,0 910.24,0 ; 890.24,3940 910.24,3940 ; 900.24,1689.09 900.24,0 ; 900.24,2250.91 900.24,3940 ; 920.24,60 900.24,0 ; 920.24,3880 900.24,3940 ; 1180.24,60 1200.24,0 ; 1180.24,3294 1200.24,3354 ; 1190.24,0 1210.24,0 ; 1190.24,3354 1210.24,3354 ; 1200.24,1396.09 1200.24,0 ; 1200.24,1957.91 1200.24,3354 ; 1220.24,60 1200.24,0 ; 1220.24,3294 1200.24,3354 ; 1480.24,60 1500.24,0 ; 1480.24,2294 1500.24,2354 ; 1490.24,0 1510.24,0 ; 1490.24,2354 1510.24,2354 ; 1500.24,896.09 1500.24,0 ; 1500.24,1457.91 1500.24,2354 ; 1520.24,60 1500.24,0 ; 1520.24,2294 1500.24,2354 ; 1780.45,60.07 1800.24,0 ; 1783.97,1090.07 1804.18,1150 ; 1790.24,0.03 1810.24,-0.03 ; 1794.18,1150.03 1814.18,1149.97 ; 1800.89,189.12 1800.24,0 ; 1803.53,960.88 1804.18,1150 ; 1820.45,59.93 1800.24,0 ; 1823.97,1089.93 1804.18,1150 ; 2080.24,-60.11 2100.24,-0.11 ; 2080.24,559.89 2100.24,499.89 ; 2090.24,-0.11 2110.24,-0.11 ; 2090.24,499.89 2110.24,499.89 ; 2100.24,-100.11 2100.24,-0.11 ; 2100.24,599.89 2100.24,499.89 ; 2120.24,-60.11 2100.24,-0.11 ; 2120.24,559.89 2100.24,499.89 ; 2380.24,59.89 2400.24,-0.11 ; 2380.24,5389.89 2400.24,5449.89 ; 2390.24,-0.11 2410.24,-0.11 ; 2390.24,5449.89 2410.24,5449.89 ; 2400.24,2443.97 2400.24,-0.11 ; 2400.24,3005.8 2400.24,5449.89 ; 2420.24,59.89 2400.24,-0.11 ; 2420.24,5389.89 2400.24,5449.89 ; 2680.24,59.89 2700.24,-0.11 ; 2680.24,6769.89 2700.24,6829.89 ; 2690.24,-0.11 2710.24,-0.11 ; 2690.24,6829.89 2710.24,6829.89 ; 2700.24,3133.97 2700.24,-0.11 ; 2700.24,3695.8 2700.24,6829.89 ; 2720.24,59.89 2700.24,-0.11 ; 2720.24,6769.89 2700.24,6829.89 ; 290.24,5099.89 310.24,5099.89 290.24,5099.89
  text "1000 (mil)" at -764,7487 h60
  text "8488.47 (mil)" at -5598.77,7475.56 h60 r0.17
  text "D=1380mil x 1610mil" at 390.24,5999.89 h60
  text "2100 (mil)" at 336.23,5883.97 h60 r90
  text "2XD=265mil" at 650.24,4829.89 h60
  text "2xD=280mil" at 940.24,4219.89 h60
  text "2XD=680mil x 990mil" at 1240.24,3269.89 h60
  text "6830 (mil)" at 2736.23,3143.97 h60 r90
  text "5450 (mil)" at 2436.23,2453.97 h60 r90
  text "5100 (mil)" at 336.23,2283.97 h60 r90
  text "4633 (mil)" at 636.23,2045.59 h60 r90
  text "3940 (mil)" at 936.23,1699.09 h60 r90
  text "3354 (mil)" at 1236.23,1406.09 h60 r90
  text "2354 (mil)" at 1536.23,906.09 h60 r90
  text "1150.007 (mil)" at 1836.91,199 h60 r89.8
  text "500 (mil)" at 2244.2,8.96 h60 r90
  text "8818.168 (mil)" at -4784.78,-328.14 h60 r359.9
IDL Stencil:
  drawing of 520 lines, arcs and shapes, not listed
